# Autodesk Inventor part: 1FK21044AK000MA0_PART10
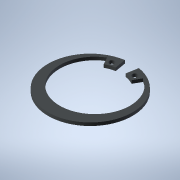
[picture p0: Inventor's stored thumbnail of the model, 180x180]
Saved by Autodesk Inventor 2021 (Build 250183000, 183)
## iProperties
Created: 2025-04
Part Number: 1FK21044AK000MA0_PART10
Material: Generic
Catalog Web Link: www.3dfindit.com
Description: -Servo synchronous motor
Document SubType Name: Modeling
Designer: psAdmin
Mass: 0.642463 g
Surface Area: 12.3927 cm^2
Volume: 0.642463 cm^3
Density: 1 g/cm^3
Appearance: PSOLRGB-212-217-219
Category: PARTsolutions
Title: 1FK21044AK000MA0_PART10
Author: Cadenas PARTsolutions
Comments: Servo synchronous motor
Sending System: PARTsolutions
Preprocessor: ST-DEVELOPER v19.3
PSOL_IDENT_0: {$CADENAS_DATA/23d-libs/siemens_ag/_cat_/87/f4/1fk21044ak000ma0.prj},216 {VTYP=3D},{NB=1FK21044AK000
PSOL_IDENT_1: MA0_PART10},{LINA=1FK21044AK000MA0_PART10},{NN=1FK21044AK000MA0_PART10},{NOPRJ=TRUE},{DATE=19.08.202
PSOL_IDENT_2: 5 14:00:48},{GEOMDATE=30.07.2025 02:00:50},{VERSION=},{LINEID=10},{WBVAR=},{WBNUMERIC=}  {NB=1FK2104
PSOL_IDENT_3: 4AK000MA0_PART10},{LINA=1FK21044AK000MA0_PART10},{KT=DUMMY},{PREVIEW=../../../_pool_/cb/72/p_d211_xx
PSOL_IDENT_4: _00434j.png},{DESCSHORT=SIMOTICS S-1FK2 HD, SINAMICS S210 3AC 400V-480V, 0.95 Nm, 6000 rpm},{DESCLON
PSOL_IDENT_5: G=SIMOTICS S-1FK2 HD servo motor M0=1.27 Nm; PN = 0.6 kW at nN=6000 rpm (380-480 V); PN = 0.4 kW at
PSOL_IDENT_6: nN=3000 rpm (200-240 V); degree of protection IP64; cylindrical shaft D19x40mm; absolute encoder 22-
PSOL_IDENT_7: bit + 12-bit multiturn (encoder AM22DQC); with OCC interface; plug size M17, rotatable; SIMOTICS S-1
PSOL_IDENT_8: FK2 servomotorfor a wide range of uses in industrial environments. SIMOTICS S‑1FK2 servomotors are c
PSOL_IDENT_9: ompact synchronous motors with a high dynamic performance that set themselves apart as a result of t
PSOL_IDENT_10: heir high power density, degree of protection and overload capability. The motors are available in t
PSOL_IDENT_11: wo variants: as High Dynamic variant (highest dynamic performance as a result of the low intrinsic m
PSOL_IDENT_12: oment of inertia for applications demanding a high dynamic performance with low moved masses) - and
PSOL_IDENT_13: as Compact variant (precise and stable closed-loop control for medium up to large moved masses as a
PSOL_IDENT_14: result of a medium intrinsic moment of inertia). SIMOTICSS‑1FK2 servomotors fully exploit their stre
PSOL_IDENT_15: ngths in a system with the SINAMICSS210 frequency converter and simple connection using the one cabl
PSOL_IDENT_16: e connection (OCC). Advantages include the short control and positioning times, fast and precise cor
PSOL_IDENT_17: rection of disturbing quantities as well as stable control with a high dynamic performance. The serv
PSOL_IDENT_18: o motors can be configured to address a wide range of requirements. For example with and without hol
PSOL_IDENT_19: ding brake, IP64 or IP65 degree of protection, singleturn or multiturn absolute encoders - to name j
PSOL_IDENT_20: ust a few. Further, the servomotors are available in different shaft heights extending from 20 to 10
PSOL_IDENT_21: 0. A shaft sealing ring is available to achieve an IP65 degree of protection and for subsequent moun
PSOL_IDENT_22: ting at the motor or as spare part. SIMOTICS - the optimum motor for each and every motion control a
PSOL_IDENT_23: pplication.},{INTNO=195125056312},{SUPPLIERALTNO=1FK2104-4AK00-0MA0},{MANUID=1FK21044AK000MA0},{MANU
PSOL_IDENT_24: NAME=Siemens},{MANUTYPEDESC=Synchronous motor 1FK2-HD 1,27 Nm},{AAU732=SIMOTICS},{AAO057=S-1FK2},{AA
PSOL_IDENT_25: U734=SIMOTICS S-1FK2 HD servo motor M0=1.27 Nm; PN = 0.6 kW at nN=6000 rpm (380-480 V); PN = 0.4 kW
PSOL_IDENT_26: at nN=3000 rpm (200-240 V); degree of protection IP64; cylindrical shaft D19x40mm; absolute encoder
PSOL_IDENT_27: 22-bit + 12-bit multiturn (encoder AM22DQC); with OCC interface; plug size M17, rotatable;},{AAW338=
PSOL_IDENT_28: Synchronous motor 1FK2-HD 1,27 Nm},{AAO742=SIMOTICS},{AAO663=4042948690994},{NOCUPEROU=1},{PRICEQUAN
PSOL_IDENT_29: TITY=1},{QUANTITYMIN=1},{QUANTITYINT=1},{CTN=85015100},{COO=DE},{AAO676=1FK2104-4AK00-0MA0},{AAO677=
PSOL_IDENT_30: Siemens AG},{ORDERUNIT=C62},{CONTENTUNIT=C62}
NB: 1FK21044AK000MA0_PART10
NT: Servo synchronous motor
NBSYN: $MANUID._PART10
LINA: 1FK21044AK000MA0_PART10
CATALOG: SIEMENS
PREVIEW: ../../../_pool_/cb/72/p_d211_xx_00434j.png
DESCSHORT: SIMOTICS S-1FK2 HD, SINAMICS S210 3AC 400V-480V, 0.95 Nm, 6000 rpm
DESCLONG: SIMOTICS S-1FK2 HD servo motor M0=1.27 Nm; PN = 0.6 kW at nN=6000 rpm (380-480 V); PN = 0.4 kW at nN=3000 rpm (200-240 V); degree of protection IP64; cylindrica
INTNO: 195125056312
SUPPLIERALTNO: 1FK2104-4AK00-0MA0
MANUID: 1FK21044AK000MA0
MANUNAME: Siemens
MANUTYPEDESC: Synchronous motor 1FK2-HD 1,27 Nm
AAU732: SIMOTICS
AAO057: S-1FK2
AAU734: SIMOTICS S-1FK2 HD servo motor M0=1.27 Nm; PN = 0.6 kW at nN=6000 rpm (380-480 V); PN = 0.4 kW at nN=3000 rpm (200-240 V); degree of protection IP64; cylindrica
AAW338: Synchronous motor 1FK2-HD 1,27 Nm
AAO742: SIMOTICS
AAO663: 4042948690994.0
NOCUPEROU: 1
PRICEQUANTITY: 1
QUANTITYMIN: 1
QUANTITYINT: 1
CTN: 85015100
COO: DE
ARTICLENO: 1FK21044AK000MA0_PART10
BOMINFO: 1FK21044AK000MA0_PART10
CREATOR: CADENAS GmbH
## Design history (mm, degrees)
feature "2025_04_17_15_37_40_0588"
body "Solid1"
